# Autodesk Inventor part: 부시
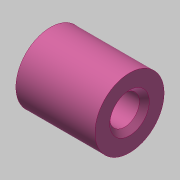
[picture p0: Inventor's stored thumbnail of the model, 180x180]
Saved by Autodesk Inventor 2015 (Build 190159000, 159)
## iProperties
Created: 2019-02
Part Number: 부시
Material: 스테인리스강
Document SubType Name: Modeling
Designer: mduedu
Density: 1 g/cm^3
Appearance: 분홍색
Author: mduedu
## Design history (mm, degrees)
sketch "스케치1"
  geometry: C1 r 3 at (0, 0); C2 r 7 at (0, 0); 1 further point
  constraints: 2 centre point, 2 coincident
  dimensions: "d0" = 6 diameter of C1; "d1" = 14 diameter of C2
extrude "돌출1" new body sketch "스케치1" stored distance "d2" = 16; taper "d3" = 0 deg
chamfer "모따기1" distance "d4" = 1; stored, may be unused: second distance "d5" = 2, angle "d6" = 45 deg
node "솔리드1"
